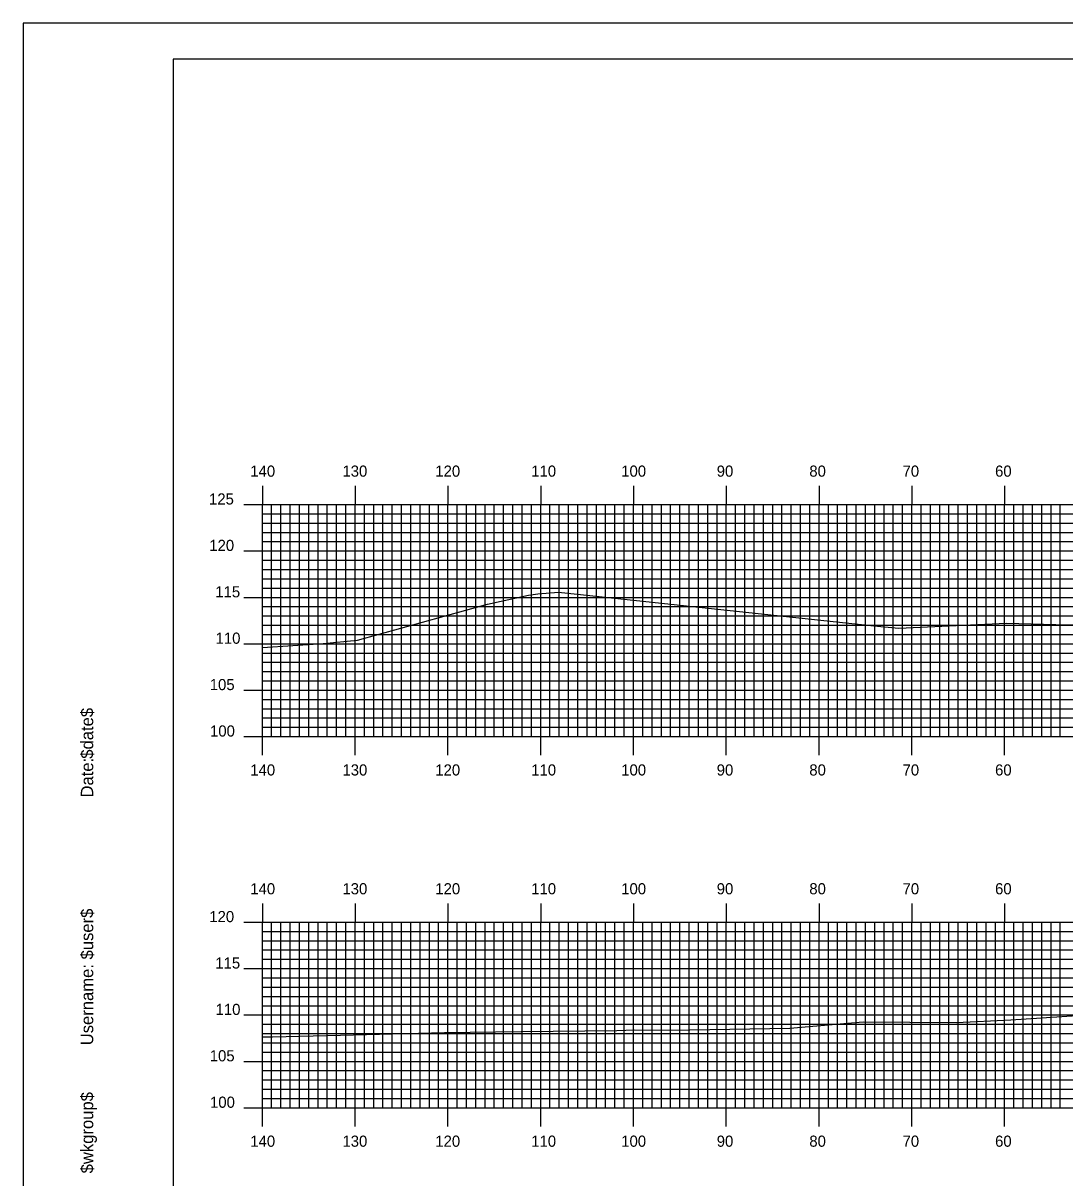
# Model space of a CAD drawing. Extents: x 1766120 to 1766463, y 442591 to 442811.
# Drawn here: x 1766119.6 to 1766231.9, y 442686.1 to 442810.5 of the extents above; entities that cross this region are included whole.
import ezdxf

# ---------------------------------------------------------------- set-up
doc = ezdxf.new("R2010")
doc.units = 0
for name, color, linetype in [('BORDER', 7, 'Continuous'), ('H_V ANNOTATION', 7, 'Continuous'), ('MAJOR', 7, 'Continuous'), ('MINOR', 7, 'Continuous'), ('PLOT BOUNDARY', 7, 'Continuous'), ('S_Roadway_Centerline', 7, 'Continuous')]:
    doc.layers.add(name, color=color, linetype=linetype)

msp = doc.modelspace()

# ---------------------------------------------------------------- linework, layer by layer
at = {"layer": 'BORDER'}
msp.add_lwpolyline([(1766135.8, 442596.67), (1766455.8, 442596.67), (1766455.8, 442806.67), (1766135.8, 442806.67)], close=True, dxfattribs=at)
at = {"layer": 'MAJOR'}
for p, q in [((1766145.4, 442760.67), (1766145.4, 442758.67)), ((1766155.4, 442760.67), (1766155.4, 442758.67)), ((1766165.4, 442760.67), (1766165.4, 442758.67)), ((1766175.4, 442760.67), (1766175.4, 442758.67)), ((1766185.4, 442760.67), (1766185.4, 442758.67)), ((1766195.4, 442760.67), (1766195.4, 442758.67)), ((1766205.4, 442760.67), (1766205.4, 442758.67)), ((1766215.4, 442760.67), (1766215.4, 442758.67)), ((1766225.4, 442760.67), (1766225.4, 442758.67)), ((1766143.39, 442758.67), (1766145.4, 442758.67)), ((1766145.4, 442758.67), (1766425.4, 442758.67)), ((1766145.4, 442733.67), (1766145.4, 442758.67)), ((1766145.4, 442733.67), (1766145.4, 442758.67)), ((1766145.4, 442758.67), (1766425.4, 442758.67)), ((1766155.4, 442733.67), (1766155.4, 442758.67)), ((1766165.4, 442733.67), (1766165.4, 442758.67)), ((1766175.4, 442733.67), (1766175.4, 442758.67)), ((1766185.4, 442733.67), (1766185.4, 442758.67)), ((1766195.4, 442733.67), (1766195.4, 442758.67)), ((1766205.4, 442733.67), (1766205.4, 442758.67)), ((1766215.4, 442733.67), (1766215.4, 442758.67)), ((1766225.4, 442733.67), (1766225.4, 442758.67)), ((1766143.39, 442753.67), (1766145.4, 442753.67)), ((1766145.4, 442753.67), (1766425.4, 442753.67)), ((1766143.39, 442748.67), (1766145.4, 442748.67)), ((1766145.4, 442748.67), (1766425.4, 442748.67)), ((1766143.39, 442743.67), (1766145.4, 442743.67)), ((1766145.4, 442743.67), (1766425.4, 442743.67)), ((1766143.39, 442738.67), (1766145.4, 442738.67)), ((1766145.4, 442738.67), (1766425.4, 442738.67)), ((1766143.39, 442733.67), (1766145.4, 442733.67)), ((1766145.4, 442733.67), (1766425.4, 442733.67)), ((1766145.4, 442733.67), (1766425.4, 442733.67)), ((1766145.4, 442731.66), (1766145.4, 442733.67)), ((1766155.4, 442731.66), (1766155.4, 442733.67)), ((1766165.4, 442731.66), (1766165.4, 442733.67)), ((1766175.4, 442731.66), (1766175.4, 442733.67)), ((1766185.4, 442731.66), (1766185.4, 442733.67)), ((1766195.4, 442731.66), (1766195.4, 442733.67)), ((1766205.4, 442731.66), (1766205.4, 442733.67)), ((1766215.4, 442731.66), (1766215.4, 442733.67)), ((1766225.4, 442731.66), (1766225.4, 442733.67)), ((1766145.4, 442715.67), (1766145.4, 442713.67)), ((1766155.4, 442715.67), (1766155.4, 442713.67)), ((1766165.4, 442715.67), (1766165.4, 442713.67)), ((1766175.4, 442715.67), (1766175.4, 442713.67)), ((1766185.4, 442715.67), (1766185.4, 442713.67)), ((1766195.4, 442715.67), (1766195.4, 442713.67)), ((1766205.4, 442715.67), (1766205.4, 442713.67)), ((1766215.4, 442715.67), (1766215.4, 442713.67)), ((1766225.4, 442715.67), (1766225.4, 442713.67)), ((1766143.39, 442713.67), (1766145.4, 442713.67)), ((1766145.4, 442713.67), (1766425.4, 442713.67)), ((1766145.4, 442693.67), (1766145.4, 442713.67)), ((1766145.4, 442693.67), (1766145.4, 442713.67)), ((1766145.4, 442713.67), (1766425.4, 442713.67)), ((1766155.4, 442693.67), (1766155.4, 442713.67)), ((1766165.4, 442693.67), (1766165.4, 442713.67)), ((1766175.4, 442693.67), (1766175.4, 442713.67)), ((1766185.4, 442693.67), (1766185.4, 442713.67)), ((1766195.4, 442693.67), (1766195.4, 442713.67)), ((1766205.4, 442693.67), (1766205.4, 442713.67)), ((1766215.4, 442693.67), (1766215.4, 442713.67)), ((1766225.4, 442693.67), (1766225.4, 442713.67)), ((1766143.39, 442708.67), (1766145.4, 442708.67)), ((1766145.4, 442708.67), (1766425.4, 442708.67)), ((1766143.39, 442703.67), (1766145.4, 442703.67)), ((1766145.4, 442703.67), (1766425.4, 442703.67)), ((1766143.39, 442698.67), (1766145.4, 442698.67)), ((1766145.4, 442698.67), (1766425.4, 442698.67)), ((1766143.39, 442693.67), (1766145.4, 442693.67)), ((1766145.4, 442693.67), (1766425.4, 442693.67)), ((1766145.4, 442693.67), (1766425.4, 442693.67)), ((1766145.4, 442691.66), (1766145.4, 442693.67)), ((1766155.4, 442691.66), (1766155.4, 442693.67)), ((1766165.4, 442691.66), (1766165.4, 442693.67)), ((1766175.4, 442691.66), (1766175.4, 442693.67)), ((1766185.4, 442691.66), (1766185.4, 442693.67)), ((1766195.4, 442691.66), (1766195.4, 442693.67)), ((1766205.4, 442691.66), (1766205.4, 442693.67)), ((1766215.4, 442691.66), (1766215.4, 442693.67)), ((1766225.4, 442691.66), (1766225.4, 442693.67))]:
    msp.add_line(p, q, dxfattribs=at)
at = {"layer": 'MINOR'}
for p, q in [((1766145.4, 442757.67), (1766425.4, 442757.67)), ((1766145.4, 442757.67), (1766147.4, 442757.67)), ((1766146.4, 442733.67), (1766146.4, 442758.67)), ((1766147.4, 442733.67), (1766147.4, 442758.67)), ((1766148.4, 442733.67), (1766148.4, 442758.67)), ((1766149.4, 442733.67), (1766149.4, 442758.67)), ((1766150.4, 442733.67), (1766150.4, 442758.67)), ((1766151.4, 442733.67), (1766151.4, 442758.67)), ((1766152.4, 442733.67), (1766152.4, 442758.67)), ((1766153.4, 442733.67), (1766153.4, 442758.67)), ((1766154.4, 442733.67), (1766154.4, 442758.67)), ((1766156.4, 442733.67), (1766156.4, 442758.67)), ((1766157.4, 442733.67), (1766157.4, 442758.67)), ((1766158.4, 442733.67), (1766158.4, 442758.67)), ((1766159.4, 442733.67), (1766159.4, 442758.67)), ((1766160.4, 442733.67), (1766160.4, 442758.67)), ((1766161.4, 442733.67), (1766161.4, 442758.67)), ((1766162.4, 442733.67), (1766162.4, 442758.67)), ((1766163.4, 442733.67), (1766163.4, 442758.67)), ((1766164.4, 442733.67), (1766164.4, 442758.67)), ((1766166.4, 442733.67), (1766166.4, 442758.67)), ((1766167.4, 442733.67), (1766167.4, 442758.67)), ((1766168.4, 442733.67), (1766168.4, 442758.67)), ((1766169.4, 442733.67), (1766169.4, 442758.67)), ((1766170.4, 442733.67), (1766170.4, 442758.67)), ((1766171.4, 442733.67), (1766171.4, 442758.67)), ((1766172.4, 442733.67), (1766172.4, 442758.67)), ((1766173.4, 442733.67), (1766173.4, 442758.67)), ((1766174.4, 442733.67), (1766174.4, 442758.67)), ((1766176.4, 442733.67), (1766176.4, 442758.67)), ((1766177.4, 442733.67), (1766177.4, 442758.67)), ((1766178.4, 442733.67), (1766178.4, 442758.67)), ((1766179.4, 442733.67), (1766179.4, 442758.67)), ((1766180.4, 442733.67), (1766180.4, 442758.67)), ((1766181.4, 442733.67), (1766181.4, 442758.67)), ((1766182.4, 442733.67), (1766182.4, 442758.67)), ((1766183.4, 442733.67), (1766183.4, 442758.67)), ((1766184.4, 442733.67), (1766184.4, 442758.67)), ((1766186.4, 442733.67), (1766186.4, 442758.67)), ((1766187.4, 442733.67), (1766187.4, 442758.67)), ((1766188.4, 442733.67), (1766188.4, 442758.67)), ((1766189.4, 442733.67), (1766189.4, 442758.67)), ((1766190.4, 442733.67), (1766190.4, 442758.67)), ((1766191.4, 442733.67), (1766191.4, 442758.67)), ((1766192.4, 442733.67), (1766192.4, 442758.67)), ((1766193.4, 442733.67), (1766193.4, 442758.67)), ((1766194.4, 442733.67), (1766194.4, 442758.67)), ((1766196.4, 442733.67), (1766196.4, 442758.67)), ((1766197.4, 442733.67), (1766197.4, 442758.67)), ((1766198.4, 442733.67), (1766198.4, 442758.67)), ((1766199.4, 442733.67), (1766199.4, 442758.67)), ((1766200.4, 442733.67), (1766200.4, 442758.67)), ((1766201.4, 442733.67), (1766201.4, 442758.67)), ((1766202.4, 442733.67), (1766202.4, 442758.67)), ((1766203.4, 442733.67), (1766203.4, 442758.67)), ((1766204.4, 442733.67), (1766204.4, 442758.67)), ((1766206.4, 442733.67), (1766206.4, 442758.67)), ((1766207.4, 442733.67), (1766207.4, 442758.67)), ((1766208.4, 442733.67), (1766208.4, 442758.67)), ((1766209.4, 442733.67), (1766209.4, 442758.67)), ((1766210.4, 442733.67), (1766210.4, 442758.67)), ((1766211.4, 442733.67), (1766211.4, 442758.67)), ((1766212.4, 442733.67), (1766212.4, 442758.67)), ((1766213.4, 442733.67), (1766213.4, 442758.67)), ((1766214.4, 442733.67), (1766214.4, 442758.67)), ((1766216.4, 442733.67), (1766216.4, 442758.67)), ((1766217.4, 442733.67), (1766217.4, 442758.67)), ((1766218.4, 442733.67), (1766218.4, 442758.67)), ((1766219.4, 442733.67), (1766219.4, 442758.67)), ((1766220.4, 442733.67), (1766220.4, 442758.67)), ((1766221.4, 442733.67), (1766221.4, 442758.67)), ((1766222.4, 442733.67), (1766222.4, 442758.67)), ((1766223.4, 442733.67), (1766223.4, 442758.67)), ((1766224.4, 442733.67), (1766224.4, 442758.67)), ((1766226.4, 442733.67), (1766226.4, 442758.67)), ((1766227.4, 442733.67), (1766227.4, 442758.67)), ((1766228.4, 442733.67), (1766228.4, 442758.67)), ((1766229.4, 442733.67), (1766229.4, 442758.67)), ((1766230.4, 442733.67), (1766230.4, 442758.67)), ((1766231.4, 442733.67), (1766231.4, 442758.67)), ((1766145.4, 442756.67), (1766425.4, 442756.67)), ((1766145.4, 442756.67), (1766147.4, 442756.67)), ((1766145.4, 442755.67), (1766425.4, 442755.67)), ((1766145.4, 442755.67), (1766147.4, 442755.67)), ((1766145.4, 442754.67), (1766425.4, 442754.67)), ((1766145.4, 442754.67), (1766147.4, 442754.67)), ((1766145.4, 442752.67), (1766425.4, 442752.67)), ((1766145.4, 442752.67), (1766147.4, 442752.67)), ((1766145.4, 442751.67), (1766425.4, 442751.67)), ((1766145.4, 442751.67), (1766147.4, 442751.67)), ((1766145.4, 442750.67), (1766425.4, 442750.67)), ((1766145.4, 442750.67), (1766147.4, 442750.67)), ((1766145.4, 442749.67), (1766425.4, 442749.67)), ((1766145.4, 442749.67), (1766147.4, 442749.67)), ((1766145.4, 442747.67), (1766425.4, 442747.67)), ((1766145.4, 442747.67), (1766147.4, 442747.67)), ((1766145.4, 442746.67), (1766425.4, 442746.67)), ((1766145.4, 442746.67), (1766147.4, 442746.67)), ((1766145.4, 442745.67), (1766425.4, 442745.67)), ((1766145.4, 442745.67), (1766147.4, 442745.67)), ((1766145.4, 442744.67), (1766425.4, 442744.67)), ((1766145.4, 442744.67), (1766147.4, 442744.67)), ((1766145.4, 442742.67), (1766425.4, 442742.67)), ((1766145.4, 442742.67), (1766147.4, 442742.67)), ((1766145.4, 442741.67), (1766425.4, 442741.67)), ((1766145.4, 442741.67), (1766147.4, 442741.67)), ((1766145.4, 442740.67), (1766425.4, 442740.67)), ((1766145.4, 442740.67), (1766147.4, 442740.67)), ((1766145.4, 442739.67), (1766425.4, 442739.67)), ((1766145.4, 442739.67), (1766147.4, 442739.67)), ((1766145.4, 442737.67), (1766425.4, 442737.67)), ((1766145.4, 442737.67), (1766147.4, 442737.67)), ((1766145.4, 442736.67), (1766425.4, 442736.67)), ((1766145.4, 442736.67), (1766147.4, 442736.67)), ((1766145.4, 442735.67), (1766425.4, 442735.67)), ((1766145.4, 442735.67), (1766147.4, 442735.67)), ((1766145.4, 442734.67), (1766425.4, 442734.67)), ((1766145.4, 442734.67), (1766147.4, 442734.67)), ((1766146.4, 442693.67), (1766146.4, 442713.67)), ((1766147.4, 442693.67), (1766147.4, 442713.67)), ((1766148.4, 442693.67), (1766148.4, 442713.67)), ((1766149.4, 442693.67), (1766149.4, 442713.67)), ((1766150.4, 442693.67), (1766150.4, 442713.67)), ((1766151.4, 442693.67), (1766151.4, 442713.67)), ((1766152.4, 442693.67), (1766152.4, 442713.67)), ((1766153.4, 442693.67), (1766153.4, 442713.67)), ((1766154.4, 442693.67), (1766154.4, 442713.67)), ((1766156.4, 442693.67), (1766156.4, 442713.67)), ((1766157.4, 442693.67), (1766157.4, 442713.67)), ((1766158.4, 442693.67), (1766158.4, 442713.67)), ((1766159.4, 442693.67), (1766159.4, 442713.67)), ((1766160.4, 442693.67), (1766160.4, 442713.67)), ((1766161.4, 442693.67), (1766161.4, 442713.67)), ((1766162.4, 442693.67), (1766162.4, 442713.67)), ((1766163.4, 442693.67), (1766163.4, 442713.67)), ((1766164.4, 442693.67), (1766164.4, 442713.67)), ((1766166.4, 442693.67), (1766166.4, 442713.67)), ((1766167.4, 442693.67), (1766167.4, 442713.67)), ((1766168.4, 442693.67), (1766168.4, 442713.67)), ((1766169.4, 442693.67), (1766169.4, 442713.67)), ((1766170.4, 442693.67), (1766170.4, 442713.67)), ((1766171.4, 442693.67), (1766171.4, 442713.67)), ((1766172.4, 442693.67), (1766172.4, 442713.67)), ((1766173.4, 442693.67), (1766173.4, 442713.67)), ((1766174.4, 442693.67), (1766174.4, 442713.67)), ((1766176.4, 442693.67), (1766176.4, 442713.67)), ((1766177.4, 442693.67), (1766177.4, 442713.67)), ((1766178.4, 442693.67), (1766178.4, 442713.67)), ((1766179.4, 442693.67), (1766179.4, 442713.67)), ((1766180.4, 442693.67), (1766180.4, 442713.67)), ((1766181.4, 442693.67), (1766181.4, 442713.67)), ((1766182.4, 442693.67), (1766182.4, 442713.67)), ((1766183.4, 442693.67), (1766183.4, 442713.67)), ((1766184.4, 442693.67), (1766184.4, 442713.67)), ((1766186.4, 442693.67), (1766186.4, 442713.67)), ((1766187.4, 442693.67), (1766187.4, 442713.67)), ((1766188.4, 442693.67), (1766188.4, 442713.67)), ((1766189.4, 442693.67), (1766189.4, 442713.67)), ((1766190.4, 442693.67), (1766190.4, 442713.67)), ((1766191.4, 442693.67), (1766191.4, 442713.67)), ((1766192.4, 442693.67), (1766192.4, 442713.67)), ((1766193.4, 442693.67), (1766193.4, 442713.67)), ((1766194.4, 442693.67), (1766194.4, 442713.67)), ((1766196.4, 442693.67), (1766196.4, 442713.67)), ((1766197.4, 442693.67), (1766197.4, 442713.67)), ((1766198.4, 442693.67), (1766198.4, 442713.67)), ((1766199.4, 442693.67), (1766199.4, 442713.67)), ((1766200.4, 442693.67), (1766200.4, 442713.67)), ((1766201.4, 442693.67), (1766201.4, 442713.67)), ((1766202.4, 442693.67), (1766202.4, 442713.67)), ((1766203.4, 442693.67), (1766203.4, 442713.67)), ((1766204.4, 442693.67), (1766204.4, 442713.67)), ((1766206.4, 442693.67), (1766206.4, 442713.67)), ((1766207.4, 442693.67), (1766207.4, 442713.67)), ((1766208.4, 442693.67), (1766208.4, 442713.67)), ((1766209.4, 442693.67), (1766209.4, 442713.67)), ((1766210.4, 442693.67), (1766210.4, 442713.67)), ((1766211.4, 442693.67), (1766211.4, 442713.67)), ((1766212.4, 442693.67), (1766212.4, 442713.67)), ((1766213.4, 442693.67), (1766213.4, 442713.67)), ((1766214.4, 442693.67), (1766214.4, 442713.67)), ((1766216.4, 442693.67), (1766216.4, 442713.67)), ((1766217.4, 442693.67), (1766217.4, 442713.67)), ((1766218.4, 442693.67), (1766218.4, 442713.67)), ((1766219.4, 442693.67), (1766219.4, 442713.67)), ((1766220.4, 442693.67), (1766220.4, 442713.67)), ((1766221.4, 442693.67), (1766221.4, 442713.67)), ((1766222.4, 442693.67), (1766222.4, 442713.67)), ((1766223.4, 442693.67), (1766223.4, 442713.67)), ((1766224.4, 442693.67), (1766224.4, 442713.67)), ((1766226.4, 442693.67), (1766226.4, 442713.67)), ((1766227.4, 442693.67), (1766227.4, 442713.67)), ((1766228.4, 442693.67), (1766228.4, 442713.67)), ((1766229.4, 442693.67), (1766229.4, 442713.67)), ((1766230.4, 442693.67), (1766230.4, 442713.67)), ((1766231.4, 442693.67), (1766231.4, 442713.67)), ((1766145.4, 442712.67), (1766425.4, 442712.67)), ((1766145.4, 442712.67), (1766147.4, 442712.67)), ((1766145.4, 442711.67), (1766425.4, 442711.67)), ((1766145.4, 442711.67), (1766147.4, 442711.67)), ((1766145.4, 442710.67), (1766425.4, 442710.67)), ((1766145.4, 442710.67), (1766147.4, 442710.67)), ((1766145.4, 442709.67), (1766425.4, 442709.67)), ((1766145.4, 442709.67), (1766147.4, 442709.67)), ((1766145.4, 442707.67), (1766425.4, 442707.67)), ((1766145.4, 442707.67), (1766147.4, 442707.67)), ((1766145.4, 442706.67), (1766425.4, 442706.67)), ((1766145.4, 442706.67), (1766147.4, 442706.67)), ((1766145.4, 442705.67), (1766425.4, 442705.67)), ((1766145.4, 442705.67), (1766147.4, 442705.67)), ((1766145.4, 442704.67), (1766425.4, 442704.67)), ((1766145.4, 442704.67), (1766147.4, 442704.67)), ((1766145.4, 442702.67), (1766425.4, 442702.67)), ((1766145.4, 442702.67), (1766147.4, 442702.67)), ((1766145.4, 442701.67), (1766425.4, 442701.67)), ((1766145.4, 442701.67), (1766147.4, 442701.67)), ((1766145.4, 442700.67), (1766425.4, 442700.67)), ((1766145.4, 442700.67), (1766147.4, 442700.67)), ((1766145.4, 442699.67), (1766425.4, 442699.67)), ((1766145.4, 442699.67), (1766147.4, 442699.67)), ((1766145.4, 442697.67), (1766425.4, 442697.67)), ((1766145.4, 442697.67), (1766147.4, 442697.67)), ((1766145.4, 442696.67), (1766425.4, 442696.67)), ((1766145.4, 442696.67), (1766147.4, 442696.67)), ((1766145.4, 442695.67), (1766425.4, 442695.67)), ((1766145.4, 442695.67), (1766147.4, 442695.67)), ((1766145.4, 442694.67), (1766425.4, 442694.67)), ((1766145.4, 442694.67), (1766147.4, 442694.67))]:
    msp.add_line(p, q, dxfattribs=at)
at = {"layer": 'PLOT BOUNDARY'}
msp.add_lwpolyline([(1766119.61, 442590.55), (1766459.61, 442590.55), (1766459.61, 442810.55), (1766119.61, 442810.55)], close=True, dxfattribs=at)
at = {"layer": 'S_Roadway_Centerline'}
for points in [[(1766145.4, 442743.28), (1766151.94, 442743.7), (1766155.65, 442744.05), (1766169.67, 442747.92), (1766174.09, 442748.9), (1766175.08, 442749.04), (1766177.32, 442749.24), (1766211.3, 442745.6), (1766213.98, 442745.34), (1766225.6, 442745.9), (1766230.93, 442745.73), (1766247.31, 442745.7)], [(1766145.4, 442701.32), (1766146.5, 442701.32), (1766153.83, 442701.48), (1766165.02, 442701.79), (1766173.28, 442701.87), (1766183.62, 442702.01), (1766185.56, 442702.07), (1766189.33, 442702.03), (1766202.24, 442702.26), (1766210.16, 442702.93), (1766220.2, 442702.84), (1766226.07, 442703.15), (1766234.88, 442703.73)]]:
    msp.add_lwpolyline(points, dxfattribs=at)

# ---------------------------------------------------------------- texts
at = {"layer": 'BORDER'}
for s, p in [('$date$', (1766127.17, 442731.28)), ('Date:', (1766127.17, 442727.1)), ('$user$', (1766127.17, 442709.65)), ('Username:', (1766127.17, 442700.4)), ('$wkgroup$', (1766127.17, 442686.6))]:
    msp.add_text(s, height=1.339, rotation=90, dxfattribs=at).set_placement(p)
at = {"layer": 'H_V ANNOTATION'}
for s, p in [('140', (1766144.1, 442761.67)), ('130', (1766154.03, 442761.67)), ('120', (1766164.04, 442761.67)), ('110', (1766174.38, 442761.67)), ('100', (1766184.08, 442761.67)), ('90', (1766194.37, 442761.67)), ('80', (1766204.35, 442761.67)), ('70', (1766214.4, 442761.67)), ('60', (1766224.37, 442761.67)), ('125', (1766139.65, 442758.67)), ('120', (1766139.68, 442753.67)), ('115', (1766140.33, 442748.67)), ('110', (1766140.36, 442743.67)), ('105', (1766139.73, 442738.67)), ('100', (1766139.76, 442733.67)), ('140', (1766144.1, 442729.47)), ('130', (1766154.03, 442729.47)), ('120', (1766164.04, 442729.47)), ('110', (1766174.38, 442729.47)), ('100', (1766184.08, 442729.47)), ('90', (1766194.37, 442729.47)), ('80', (1766204.35, 442729.47)), ('70', (1766214.4, 442729.47)), ('60', (1766224.37, 442729.47)), ('140', (1766144.1, 442716.67)), ('130', (1766154.03, 442716.67)), ('120', (1766164.04, 442716.67)), ('110', (1766174.38, 442716.67)), ('100', (1766184.08, 442716.67)), ('90', (1766194.37, 442716.67)), ('80', (1766204.35, 442716.67)), ('70', (1766214.4, 442716.67)), ('60', (1766224.37, 442716.67)), ('120', (1766139.68, 442713.67)), ('115', (1766140.33, 442708.67)), ('110', (1766140.36, 442703.67)), ('105', (1766139.73, 442698.67)), ('100', (1766139.76, 442693.67)), ('140', (1766144.1, 442689.47)), ('130', (1766154.03, 442689.47)), ('120', (1766164.04, 442689.47)), ('110', (1766174.38, 442689.47)), ('100', (1766184.08, 442689.47)), ('90', (1766194.37, 442689.47)), ('80', (1766204.35, 442689.47)), ('70', (1766214.4, 442689.47)), ('60', (1766224.37, 442689.47))]:
    msp.add_text(s, height=1.2, dxfattribs=at).set_placement(p)
at = {"layer": 'MAJOR'}
for p in [(1766145.39, 442733.67), (1766145.39, 442693.67)]:
    msp.add_text('-', height=0.012, dxfattribs=at).set_placement(p)

doc.saveas('drawing.dxf')
